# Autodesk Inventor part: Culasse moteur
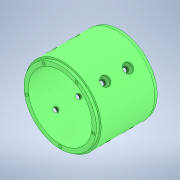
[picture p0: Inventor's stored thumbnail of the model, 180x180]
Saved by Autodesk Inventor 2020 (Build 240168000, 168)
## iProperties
Created: 2003-05
Part Number: Culasse moteur
Material: Générique
Document SubType Name: Modeling
Designer: Bruno
Density: 1 g/cm^3
Appearance: Par défaut
Author: Bruno
Sending System: SolidWorks 2011
Last Author: frederic
Last Saved: 2012-02-20
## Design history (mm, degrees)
feature "Chanfrein2"
node "Solide1"
